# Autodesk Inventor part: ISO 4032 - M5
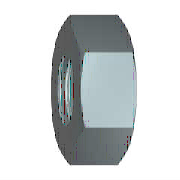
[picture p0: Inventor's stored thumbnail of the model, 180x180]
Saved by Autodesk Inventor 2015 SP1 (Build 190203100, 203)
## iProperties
Created: 2014-02
Part Number: ISO 4032 - M5
Material: Stainless Steel, 440C
Description: Hexagon nuts, style 1 - Product grades A and B
Document SubType Name: Modeling
Standard: ISO 4032
Designer: davidvaughan
Standard Revision: Third edition 1999-08-15
Standards Organization: ISO
Language: en-US
Size Designation: M5
Categories: <MemberInstance><Categories><Category DisplayName="Fasteners" InternalName="e4da775c-781d-43d5-af7c-5136215cf5a6" Mnemonic="FSTN"><Category DisplayName="Nuts" I
Density: 7.75 g/cm^3
Appearance: Semi-Polished
IsCustomPart: 1
Author: davidvaughan
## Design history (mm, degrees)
sketch "Sketch1"
  geometry: L1 (-4.619, 0)-(-2.309, 4); L2 (-2.309, 4)-(2.309, 4); L3 (2.309, 4)-(4.619, 0); L4 (4.619, 0)-(2.309, -4); L5 (2.309, -4)-(-2.309, -4); L6 (-2.309, -4)-(-4.619, 0); 2 further points
  constraints: 12 end point, 1 coincident, 1 horizontal, 11 other
  dimensions: "d0" = 9.2376 distance of L3.end L1.start (= 1.1547 x SW)
extrude "Body" new body sketch "Sketch1" distance "d1" = 4.7 (= KOH); taper "d2" = 0 deg
sketch "Sketch2"
  geometry: L1 (0, 2.309)-(0, 4.619) reference; L2 (0, 4.619)-(4.7, 4.619) reference; L3 (4.7, 2.309)-(4.7, 4.619) reference; L4 (-0.94, 0)-(5.64, 0) reference; L5 (0.675, 4.619)-(0, 3.45); L6 (4.025, 4.619)-(4.7, 3.45)
  constraints: 4 end point, 4 point on line
  dimensions: "d3" = 30 deg angle of L1 L5 (= ANG1); "d4" = 30 deg angle of L3 L6 (= ANG2); "d5" = 6.9 diameter of L5.end L4 (= SW0); "d6" = 6.9 diameter of L6.end L4 (= SW01)
revolve "Chamfer1" sketch "Sketch2" stored, may be unused: angle "d7" = 90 deg
sketch "Sketch3"
  geometry: 4 further points
  constraints: 1 coincident, 1 other
hole "Thread" sketch "Sketch3" at (0, 0) diameter "d25" = 4.134; stored, may be unused: countersink angle "d29" = 82 deg, drill point angle "d31" = 118 deg; dims "d26" = 6, "d27" = 4, "d28" = 2, "d30" = 8
workaxis "Work Axis1"
workplane "Work Plane1"
body "Solid1"
chamfer "Chamfer2" distance "d8" = 0.43301 (= -0.5 x GD1 + 0.5 x NND); stored, may be unused: angle "d9" = 30 deg, second distance "d40" = 0.43301 (= -0.5 x GD1 + 0.5 x NND)
chamfer "Chamfer3" distance "d10" = 0.43301 (= -0.5 x GD1 + 0.5 x NND); stored, may be unused: angle "d11" = 30 deg, second distance "d41" = 0.43301 (= -0.5 x GD1 + 0.5 x NND)
other parameters: "ANG1" = 30 deg [user parameter; used in 1 equation term], "ANG2" = 30 deg [user parameter; used in 1 equation term], "NND" = 5 [user parameter; used in 4 equation terms], "KOH" = 4.7 [user parameter; used in 1 equation term], "SW" = 8 [user parameter; used in 2 equation terms], "SW0" = 6.9 [user parameter; used in 2 equation terms], "SW01" = 6.9 (= SW0) [user parameter; used in 1 equation term], "GD1" = 4.13397 (computed from THREADDIA, PTC, TOA) [user parameter; used in 4 equation terms], "d13" = 0, "d14" = 0, "d39" = 0, "d42" = 0, "GUL" = 0.43301 (= 0.541266 x PTC) [user parameter], "TPU" = 12.5 (computed from PTC) [user parameter], "THREADDIA" = 5 [user parameter; used in 1 equation term], "TOA" = 30 deg [user parameter; used in 1 equation term], "PTC" = 0.8 [user parameter; used in 4 equation terms], "E0" = 9.24 (= 1.155 x SW) [user parameter], "GAL" = 0.43301 (= 0.541266 x PTC) [user parameter]
